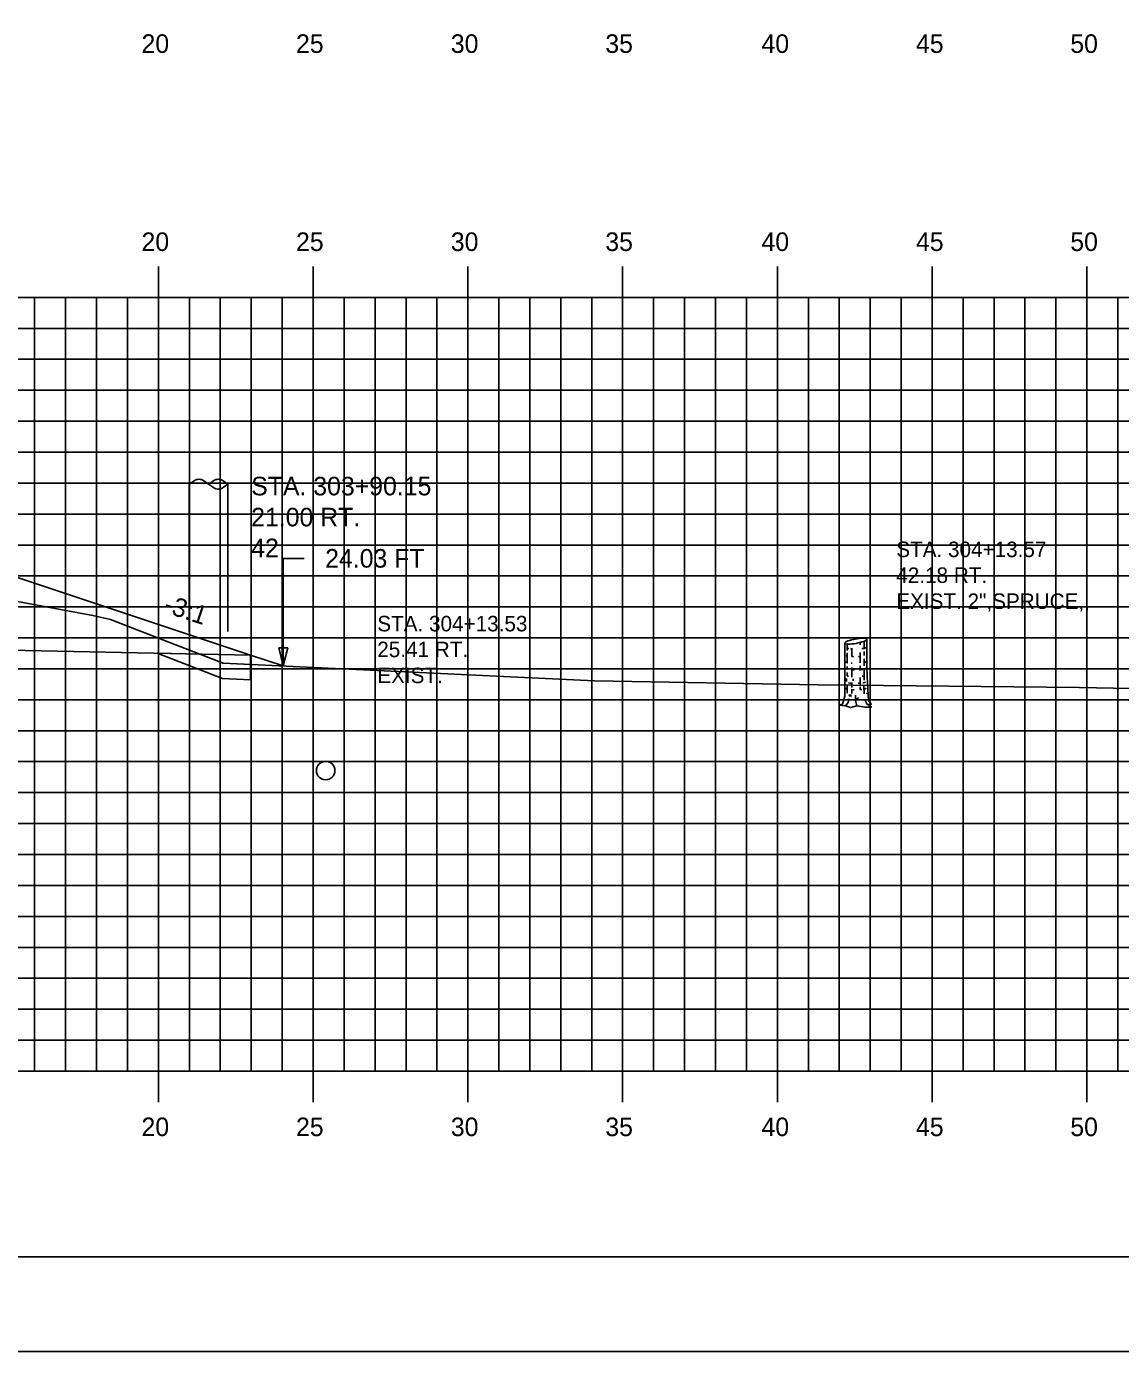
# Model space of a CAD drawing. Extents: x 1136989 to 1137159, y 608981 to 609091.
# Drawn here: x 1137087.88 to 1137123.23, y 608981.28 to 609024.09 of the extents above; entities that cross this region are included whole.
import ezdxf

# ---------------------------------------------------------------- set-up
doc = ezdxf.new("R2010")
doc.units = 0
for name, color, linetype in [('ANNOTATION', 7, 'Continuous'), ('BORDER', 7, 'Continuous'), ('D_Roadway_SlopeLines', 7, 'Continuous'), ('D_Roadway_SubGrade', 7, 'Continuous'), ('D_Text_Monospaced', 7, 'Continuous'), ('D_Text_Standard', 7, 'Continuous'), ('D_Utilities_Pole_Joint_Rt', 7, 'Continuous'), ('H_V ANNOTATION', 7, 'Continuous'), ('MAJOR', 7, 'Continuous'), ('MINOR', 7, 'Continuous'), ('PLOT BOUNDARY', 7, 'Continuous'), ('S_Drainage_Invert', 7, 'Continuous'), ('S_Roadway_Centerline', 7, 'Continuous'), ('S_Trees_Conifer_NonPay', 7, 'Continuous'), ('SHADING', 7, 'Continuous')]:
    doc.layers.add(name, color=color, linetype=linetype)

msp = doc.modelspace()

# ---------------------------------------------------------------- linework, layer by layer
at = {"layer": 'BORDER'}
msp.add_lwpolyline([(1136997.14, 608984.335), (1137157.14, 608984.335), (1137157.14, 609089.335), (1136997.14, 609089.335)], close=True, dxfattribs=at)
at = {"layer": 'D_Roadway_SlopeLines'}
msp.add_line((1137095.119, 609003.78), (1137095.119, 609003.479), dxfattribs=at)
for points in [[(1137095.119, 609003.479), (1137095.119, 609002.979), (1137094.213, 609003.023), (1137092.096, 609003.841)], [(1137095.119, 609003.78), (1137096.172, 609003.429)]]:
    msp.add_lwpolyline(points, dxfattribs=at)
at = {"layer": 'D_Roadway_SubGrade'}
msp.add_lwpolyline([(1137083.14, 609006.103), (1137083.14, 609006.27), (1137087.14, 609006.19), (1137087.14, 609006.44), (1137087.14, 609006.44), (1137095.119, 609003.78), (1137083.14, 609004.02)], close=True, dxfattribs=at)
at = {"layer": 'D_Text_Standard'}
msp.add_lwpolyline([(1137096.172, 609003.429), (1137096.168, 609006.904), (1137096.848, 609006.904)], dxfattribs=at)
msp.add_lwpolyline([(1137096.172, 609003.429), (1137096.026, 609004.011), (1137096.317, 609004.011)], close=True, dxfattribs=at)
at = {"layer": 'D_Utilities_Pole_Joint_Rt'}
for p, q in [((1137093.138, 609009.299), (1137093.294, 609009.409)), ((1137093.138, 609004.541), (1137093.138, 609009.299)), ((1137093.606, 609009.409), (1137093.762, 609009.299)), ((1137093.918, 609009.409), (1137093.762, 609009.299)), ((1137093.762, 609009.299), (1137093.918, 609009.188)), ((1137094.388, 609009.299), (1137094.231, 609009.409)), ((1137094.231, 609009.188), (1137094.388, 609009.299)), ((1137094.388, 609004.541), (1137094.388, 609009.299))]:
    msp.add_line(p, q, dxfattribs=at)
for centre, start, end in [((1137093.45, 609009.188), 90, 125.2644), ((1137093.45, 609009.188), 54.7356, 90), ((1137094.075, 609009.188), 90, 125.2644), ((1137094.075, 609009.188), 54.7356, 90), ((1137094.075, 609009.409), 234.7356, 270), ((1137094.075, 609009.409), 270, 305.2644)]:
    msp.add_arc(centre, 0.271, start, end, dxfattribs=at)
at = {"layer": 'MAJOR'}
for p, q in [((1137092.14, 609016.337), (1137092.14, 609015.335)), ((1137097.14, 609016.337), (1137097.14, 609015.335)), ((1137102.14, 609016.337), (1137102.14, 609015.335)), ((1137107.14, 609016.337), (1137107.14, 609015.335)), ((1137112.14, 609016.337), (1137112.14, 609015.335)), ((1137117.14, 609016.337), (1137117.14, 609015.335)), ((1137122.14, 609016.337), (1137122.14, 609015.335)), ((1137002.14, 609015.335), (1137142.14, 609015.335)), ((1137002.14, 609015.335), (1137142.14, 609015.335)), ((1137092.14, 608990.335), (1137092.14, 609015.335)), ((1137097.14, 608990.335), (1137097.14, 609015.335)), ((1137102.14, 608990.335), (1137102.14, 609015.335)), ((1137107.14, 608990.335), (1137107.14, 609015.335)), ((1137112.14, 608990.335), (1137112.14, 609015.335)), ((1137117.14, 608990.335), (1137117.14, 609015.335)), ((1137122.14, 608990.335), (1137122.14, 609015.335)), ((1137002.14, 609010.335), (1137142.14, 609010.335)), ((1137002.14, 609005.335), (1137142.14, 609005.335)), ((1137002.14, 609000.335), (1137142.14, 609000.335)), ((1137002.14, 608995.335), (1137142.14, 608995.335)), ((1137002.14, 608990.335), (1137142.14, 608990.335)), ((1137002.14, 608990.335), (1137142.14, 608990.335)), ((1137092.14, 608989.333), (1137092.14, 608990.335)), ((1137097.14, 608989.333), (1137097.14, 608990.335)), ((1137102.14, 608989.333), (1137102.14, 608990.335)), ((1137107.14, 608989.333), (1137107.14, 608990.335)), ((1137112.14, 608989.333), (1137112.14, 608990.335)), ((1137117.14, 608989.333), (1137117.14, 608990.335)), ((1137122.14, 608989.333), (1137122.14, 608990.335))]:
    msp.add_line(p, q, dxfattribs=at)
at = {"layer": 'MINOR'}
for p, q in [((1137088.14, 608990.335), (1137088.14, 609015.335)), ((1137089.14, 608990.335), (1137089.14, 609015.335)), ((1137090.14, 608990.335), (1137090.14, 609015.335)), ((1137091.14, 608990.335), (1137091.14, 609015.335)), ((1137093.14, 608990.335), (1137093.14, 609015.335)), ((1137094.14, 608990.335), (1137094.14, 609015.335)), ((1137095.14, 608990.335), (1137095.14, 609015.335)), ((1137096.14, 608990.335), (1137096.14, 609015.335)), ((1137098.14, 608990.335), (1137098.14, 609015.335)), ((1137099.14, 608990.335), (1137099.14, 609015.335)), ((1137100.14, 608990.335), (1137100.14, 609015.335)), ((1137101.14, 608990.335), (1137101.14, 609015.335)), ((1137103.14, 608990.335), (1137103.14, 609015.335)), ((1137104.14, 608990.335), (1137104.14, 609015.335)), ((1137105.14, 608990.335), (1137105.14, 609015.335)), ((1137106.14, 608990.335), (1137106.14, 609015.335)), ((1137108.14, 608990.335), (1137108.14, 609015.335)), ((1137109.14, 608990.335), (1137109.14, 609015.335)), ((1137110.14, 608990.335), (1137110.14, 609015.335)), ((1137111.14, 608990.335), (1137111.14, 609015.335)), ((1137113.14, 608990.335), (1137113.14, 609015.335)), ((1137114.14, 608990.335), (1137114.14, 609015.335)), ((1137115.14, 608990.335), (1137115.14, 609015.335)), ((1137116.14, 608990.335), (1137116.14, 609015.335)), ((1137118.14, 608990.335), (1137118.14, 609015.335)), ((1137119.14, 608990.335), (1137119.14, 609015.335)), ((1137120.14, 608990.335), (1137120.14, 609015.335)), ((1137121.14, 608990.335), (1137121.14, 609015.335)), ((1137123.14, 608990.335), (1137123.14, 609015.335)), ((1137002.14, 609014.335), (1137142.14, 609014.335)), ((1137002.14, 609013.335), (1137142.14, 609013.335)), ((1137002.14, 609012.335), (1137142.14, 609012.335)), ((1137002.14, 609011.335), (1137142.14, 609011.335)), ((1137002.14, 609009.335), (1137142.14, 609009.335)), ((1137002.14, 609008.335), (1137142.14, 609008.335)), ((1137002.14, 609007.335), (1137142.14, 609007.335)), ((1137002.14, 609006.335), (1137142.14, 609006.335)), ((1137002.14, 609004.335), (1137142.14, 609004.335)), ((1137002.14, 609003.335), (1137142.14, 609003.335)), ((1137002.14, 609002.335), (1137142.14, 609002.335)), ((1137002.14, 609001.335), (1137142.14, 609001.335)), ((1137002.14, 608999.335), (1137142.14, 608999.335)), ((1137002.14, 608998.335), (1137142.14, 608998.335)), ((1137002.14, 608997.335), (1137142.14, 608997.335)), ((1137002.14, 608996.335), (1137142.14, 608996.335)), ((1137002.14, 608994.335), (1137142.14, 608994.335)), ((1137002.14, 608993.335), (1137142.14, 608993.335)), ((1137002.14, 608992.335), (1137142.14, 608992.335)), ((1137002.14, 608991.335), (1137142.14, 608991.335))]:
    msp.add_line(p, q, dxfattribs=at)
at = {"layer": 'PLOT BOUNDARY'}
msp.add_lwpolyline([(1136989.047, 608981.276), (1137159.047, 608981.276), (1137159.047, 609091.276), (1136989.047, 609091.276)], close=True, dxfattribs=at)
at = {"layer": 'S_Drainage_Invert'}
msp.add_circle((1137097.545, 609000.047), 0.3, dxfattribs=at)
at = {"layer": 'S_Roadway_Centerline'}
msp.add_lwpolyline([(1137002.14, 609000.098), (1137009.532, 609000.178), (1137012.739, 609000.098), (1137016.466, 609000.152), (1137036.626, 609000.169), (1137038.714, 609000.163), (1137041.2, 609000.115), (1137042.648, 609000.935), (1137061.665, 609005.086), (1137063.035, 609005.338), (1137063.585, 609005.359), (1137073.925, 609005.86), (1137075.247, 609005.88), (1137084.732, 609006.033), (1137090.016, 609005.053), (1137090.597, 609004.926), (1137092.675, 609004.125), (1137094.237, 609003.522), (1137106.232, 609002.947), (1137113.452, 609002.818), (1137121.89, 609002.73), (1137136.879, 609002.44), (1137141.584, 609002.392), (1137142.14, 609002.4)], dxfattribs=at)
at = {"layer": 'S_Trees_Conifer_NonPay'}
for p, q in [((1137114.394, 609004.13), (1137114.394, 609003.925)), ((1137114.55, 609004.005), (1137114.55, 609003.732)), ((1137114.812, 609004.185), (1137114.812, 609004.106)), ((1137114.947, 609003.896), (1137114.947, 609003.766)), ((1137114.394, 609003.852), (1137114.394, 609003.52)), ((1137114.812, 609003.857), (1137114.812, 609003.532)), ((1137114.947, 609003.657), (1137114.947, 609003.431)), ((1137114.376, 609003.026), (1137114.376, 609002.929)), ((1137114.394, 609003.406), (1137114.394, 609003.328)), ((1137114.394, 609003.213), (1137114.394, 609003.104)), ((1137114.55, 609003.378), (1137114.55, 609003.06)), ((1137114.592, 609003.015), (1137114.592, 609002.946)), ((1137114.812, 609003.431), (1137114.812, 609003.277)), ((1137114.812, 609003.049), (1137114.812, 609002.815)), ((1137114.947, 609003.339), (1137114.947, 609002.963)), ((1137114.394, 609002.815), (1137114.394, 609002.547)), ((1137114.55, 609002.89), (1137114.55, 609002.73)), ((1137114.55, 609002.673), (1137114.55, 609002.541)), ((1137114.812, 609002.753), (1137114.812, 609002.667)), ((1137114.928, 609002.77), (1137114.945, 609002.524)), ((1137115.007, 609002.541), (1137115.067, 609002.548))]:
    msp.add_line(p, q, dxfattribs=at)
for points in [[(1137114.315, 609004.164), (1137114.315, 609002.446), (1137114.245, 609002.19), (1137114.126, 609002.156), (1137114.342, 609002.139), (1137114.502, 609002.081), (1137114.711, 609002.139), (1137114.974, 609002.092), (1137115.18, 609002.098), (1137115.028, 609002.201), (1137114.957, 609002.354)], [(1137114.947, 609004.226), (1137114.947, 609004.129), (1137114.947, 609003.964)], [(1137115.058, 609002.181), (1137115.174, 609002.19), (1137115.082, 609002.315), (1137115.048, 609002.856), (1137115.028, 609003.373), (1137115.028, 609004.292)], [(1137114.342, 609002.139), (1137114.432, 609002.251), (1137114.449, 609002.366)], [(1137114.474, 609002.502), (1137114.462, 609002.457), (1137114.513, 609002.446), (1137114.513, 609002.508)], [(1137114.711, 609002.139), (1137114.667, 609002.315), (1137114.661, 609002.48)], [(1137114.665, 609002.365), (1137114.734, 609002.36), (1137114.752, 609002.412)]]:
    msp.add_lwpolyline(points, dxfattribs=at)
for centre, radius, start, end in [((1137114.987, 609002.502), 1.825, 100.3798, 108.3946), ((1137114.987, 609002.502), 1.825, 92.3651, 100.3798), ((1137114.922, 609004.08), 0.245, 70.3798, 92.3651), ((1137114.98, 609004.243), 0.0729, 59.1402, 70.3798), ((1137115.004, 609004.283), 0.0263, 40.3798, 59.1402), ((1137115.01, 609004.288), 0.0186, 26.433, 40.3798), ((1137115.014, 609004.29), 0.0141, 10.3798, 26.433), ((1137114.333, 609004.164), 0.0186, 160.3798, 174.3267), ((1137114.329, 609004.164), 0.0141, 174.3267, 190.3798), ((1137114.329, 609004.164), 0.0141, 190.3798, 206.433), ((1137114.33, 609004.048), 0.0143, 180, 196.0515), ((1137114.341, 609004.161), 0.0263, 141.6195, 160.3798), ((1137114.333, 609004.166), 0.0186, 206.433, 220.3798), ((1137114.339, 609004.171), 0.0263, 220.3798, 239.1402), ((1137114.377, 609004.132), 0.0729, 130.3798, 141.6195), ((1137114.363, 609004.211), 0.0729, 239.1402, 250.3798), ((1137114.489, 609004.001), 0.245, 108.3946, 130.3798), ((1137114.42, 609004.374), 0.245, 250.3798, 272.3651), ((1137114.457, 609004.237), 0.245, 254.8461, 261.8968), ((1137114.672, 609005.744), 1.767, 261.8968, 262.605), ((1137114.355, 609005.952), 1.825, 272.3651, 280.3798), ((1137114.672, 609005.744), 1.767, 264.3267, 266.0499), ((1137114.355, 609005.952), 1.825, 280.3798, 288.3946), ((1137114.672, 609005.744), 1.767, 276.2449, 278.1032), ((1137114.886, 609004.237), 0.245, 278.1032, 284.1859), ((1137114.854, 609004.453), 0.245, 288.3946, 310.3798), ((1137114.886, 609004.237), 0.245, 291.7653, 300), ((1137114.972, 609004.089), 0.0738, 300, 311.2506), ((1137114.966, 609004.322), 0.0729, 310.3798, 321.6195), ((1137115.003, 609004.054), 0.0267, 311.2506, 330), ((1137115.002, 609004.293), 0.0263, 321.6195, 340.3798), ((1137115.01, 609004.05), 0.0189, 330, 343.9485), ((1137115.009, 609004.29), 0.0186, 340.3798, 354.3267), ((1137115.014, 609004.29), 0.0141, 354.3267, 10.3798), ((1137114.33, 609003.582), 0.0143, 180, 196.0515), ((1137114.334, 609003.584), 0.0189, 196.0515, 210), ((1137114.341, 609003.588), 0.0267, 210, 228.7494), ((1137114.372, 609003.623), 0.0738, 228.7494, 240), ((1137114.457, 609003.771), 0.245, 240, 246.7914), ((1137114.459, 609003.985), 0.245, 244.3148, 257.5375), ((1137114.457, 609003.771), 0.245, 254.8461, 257.5454), ((1137114.672, 609005.278), 1.767, 265.2285, 266.1325), ((1137114.674, 609005.492), 1.767, 265.8991, 267.5962), ((1137114.674, 609005.492), 1.767, 272.7221, 274.4847), ((1137114.886, 609003.771), 0.245, 284.1859, 300), ((1137114.972, 609003.623), 0.0738, 300, 311.2506), ((1137115.003, 609003.588), 0.0267, 311.2506, 330), ((1137115.005, 609003.801), 0.0267, 311.2506, 330), ((1137115.01, 609003.584), 0.0189, 330, 343.9485), ((1137115.012, 609003.798), 0.0189, 330, 343.9485), ((1137114.33, 609003.371), 0.0143, 180, 196.0515), ((1137114.334, 609003.372), 0.0189, 196.0515, 210), ((1137114.341, 609003.376), 0.0267, 210, 228.7494), ((1137114.372, 609003.412), 0.0738, 228.7494, 240), ((1137114.457, 609003.56), 0.245, 240, 254.9514), ((1137114.457, 609003.34), 0.245, 254.9814, 261.8968), ((1137114.671, 609004.848), 1.767, 261.8968, 262.45), ((1137114.672, 609005.067), 1.767, 266.0429, 268.5525), ((1137114.672, 609005.067), 1.767, 274.5361, 277.0026), ((1137114.671, 609004.848), 1.767, 276.7966, 278.1032), ((1137114.886, 609003.34), 0.245, 278.1032, 284.3207), ((1137114.887, 609003.56), 0.245, 292.1924, 300), ((1137114.972, 609003.412), 0.0738, 300, 311.2506), ((1137115.003, 609003.376), 0.0267, 311.2506, 330), ((1137115.01, 609003.372), 0.0189, 330, 343.9485), ((1137114.328, 609002.729), 0.0143, 180, 196.0515), ((1137114.329, 609002.935), 0.0143, 180, 196.0515), ((1137114.333, 609002.73), 0.0189, 196.0515, 210), ((1137114.34, 609002.734), 0.0267, 210, 228.7494), ((1137114.371, 609002.769), 0.0738, 228.7494, 240), ((1137114.456, 609002.917), 0.245, 240, 249.1675), ((1137114.671, 609004.631), 1.767, 262.2622, 265.0496), ((1137114.671, 609004.425), 1.767, 266.0862, 268.2187), ((1137114.671, 609004.631), 1.767, 272.6293, 274.5612), ((1137114.671, 609004.425), 1.767, 274.2776, 276.3006), ((1137114.671, 609004.631), 1.767, 277.63, 278.1032), ((1137114.886, 609003.123), 0.245, 278.1032, 294.6056), ((1137114.885, 609002.917), 0.245, 284.0684, 300), ((1137114.971, 609002.769), 0.0738, 300, 302.05)]:
    msp.add_arc(centre, radius, start, end, dxfattribs=at)
at = {"layer": 'SHADING'}
msp.add_line((1137093.483, 609003.813), (1137092.096, 609003.841), dxfattribs=at)
for points in [[(1137092.096, 609003.841), (1137094.213, 609003.023), (1137095.119, 609002.979), (1137095.119, 609003.479)], [(1137095.119, 609003.479), (1137094.237, 609003.522), (1137093.483, 609003.813)]]:
    msp.add_lwpolyline(points, dxfattribs=at)

# ---------------------------------------------------------------- texts
at = {"layer": 'ANNOTATION'}
msp.add_text('-3:1', height=0.6, rotation=341.5652, dxfattribs=at).set_placement((1137092.279, 609005.181))
at = {"layer": 'D_Text_Monospaced'}
for s, height, p in [('STA. 304+13.57', 0.49998, (1137115.981, 609006.944)), ('42.18 RT.', 0.5, (1137115.981, 609006.11)), ('EXIST. 2",SPRUCE,,', 0.49998, (1137115.981, 609005.27)), ('STA. 304+13.53', 0.49998, (1137099.212, 609004.545)), ('25.41 RT.', 0.5, (1137099.212, 609003.711)), ('EXIST. ', 0.5, (1137099.212, 609002.871))]:
    msp.add_text(s, height=height, dxfattribs=at).set_placement(p)
at = {"layer": 'D_Text_Standard'}
for s, p in [('STA. 303+90.15', (1137095.138, 609008.939)), ('21.00 RT.', (1137095.138, 609007.937)), ('42 ', (1137095.138, 609006.941)), ('24.03 FT', (1137097.528, 609006.604))]:
    msp.add_text(s, height=0.6, dxfattribs=at).set_placement(p)
at = {"layer": 'H_V ANNOTATION'}
for s, p in [('20', (1137091.594, 609023.235)), ('25', (1137096.586, 609023.235)), ('30', (1137101.588, 609023.235)), ('35', (1137106.58, 609023.235)), ('40', (1137111.626, 609023.235)), ('45', (1137116.618, 609023.235)), ('50', (1137121.604, 609023.235)), ('20', (1137091.594, 609016.835)), ('25', (1137096.586, 609016.835)), ('30', (1137101.588, 609016.835)), ('35', (1137106.58, 609016.835)), ('40', (1137111.626, 609016.835)), ('45', (1137116.618, 609016.835)), ('50', (1137121.604, 609016.835)), ('20', (1137091.594, 608988.235)), ('25', (1137096.586, 608988.235)), ('30', (1137101.588, 608988.235)), ('35', (1137106.58, 608988.235)), ('40', (1137111.626, 608988.235)), ('45', (1137116.618, 608988.235)), ('50', (1137121.604, 608988.235))]:
    msp.add_text(s, height=0.6, dxfattribs=at).set_placement(p)

doc.saveas('drawing.dxf')
